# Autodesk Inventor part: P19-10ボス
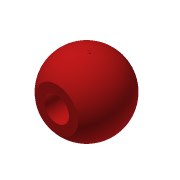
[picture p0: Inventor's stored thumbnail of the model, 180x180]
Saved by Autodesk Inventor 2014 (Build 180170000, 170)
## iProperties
Created: 2008-07
Part Number: P19-10ボス
Document SubType Name: Modeling
Designer: y-shimohigashi
Density: 1 g/cm^3
Stock Number: P19-10ボス
Material: 一般
Appearance: 淡い赤-オレンジ
Author: y-shimohigashi
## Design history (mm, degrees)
sketch "スケッチ1"
  geometry: L1 (0, 12)-(0, 3.253); L2 (0, 3.253)-(4, 3.253); L3 (4, 3.253)-(4, -9.747); L4 (4, -9.747)-(7, -9.747); A1 r 12 centre (0, 0) between (7, -9.747) and (0, 12); 1 further point
  constraints: 8 end point, 2 parallel, 2 point on circle, 1 centre point, 1 coincident, 1 perpendicular, 1 point on line, 1 vertical
  dimensions: "d0" = 4 distance of L1.end L2.end; "d1" = 3 distance of L3.end L4.end; "d2" = 13 distance of L2.end L3.end; "d3" = 12 radius of A1
revolve "回転1" sketch "スケッチ1" stored, may be unused: angle "d4" = 90 deg
node "ソリッド1"
node "ソリッド ボディ"
node "サーフェス ボディ"
